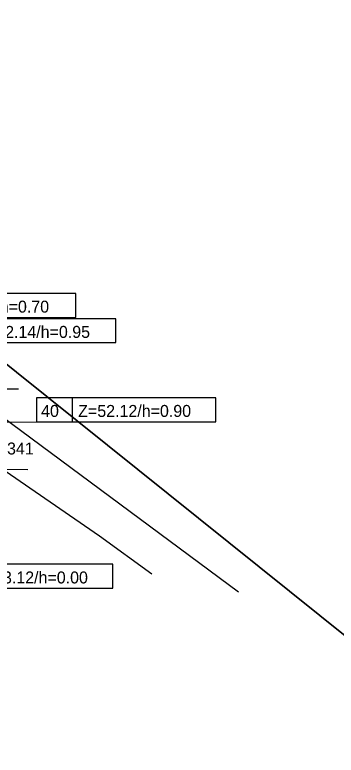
# Model space of a CAD drawing. Extents: x 592082 to 595437, y 6463338 to 6467739.
# Drawn here: x 592422.46 to 592441.27, y 6466209.39 to 6466252.72 of the extents above; entities that cross this region are included whole.
import ezdxf

# ---------------------------------------------------------------- set-up
doc = ezdxf.new("R2010")
doc.units = 0
for name, color, linetype in [('ABIJOONIS', 7, 'Continuous'), ('MPKAABEL', 7, 'Continuous'), ('PIIR', 7, 'Continuous'), ('TEE', 7, 'Continuous')]:
    doc.layers.add(name, color=color, linetype=linetype)

msp = doc.modelspace()

# ---------------------------------------------------------------- linework, layer by layer
at = {"layer": 'ABIJOONIS'}
for points in [[(592405.513, 6466234.668), (592415.526, 6466235.012), (592426.026, 6466235.012), (592426.026, 6466236.412), (592415.526, 6466236.412), (592415.526, 6466235.012)], [(592405.926, 6466232.295), (592417.871, 6466233.534), (592428.371, 6466233.534), (592428.371, 6466234.934), (592417.871, 6466234.934), (592417.871, 6466233.534)], [(592406.326, 6466228.858), (592423.735, 6466228.908), (592434.235, 6466228.908), (592434.235, 6466230.308), (592423.735, 6466230.308), (592423.735, 6466228.908)], [(592425.835, 6466228.908), (592425.835, 6466230.308)], [(592408.036, 6466224.039), (592417.694, 6466219.162), (592428.194, 6466219.162), (592428.194, 6466220.562), (592417.694, 6466220.562), (592417.694, 6466219.162)]]:
    msp.add_lwpolyline(points, dxfattribs=at)
at = {"layer": 'MPKAABEL'}
for points in [[(592405.954, 6466229.159), (592416.935, 6466230.832), (592422.676, 6466230.832)], [(592406.175, 6466228.523), (592418.139, 6466226.158), (592423.218, 6466226.12)]]:
    msp.add_lwpolyline(points, dxfattribs=at)
at = {"layer": 'PIIR'}
for points in [[(592657.41, 6466097.76), (592652.06, 6466095.54), (592644.52, 6466091.39), (592640.79, 6466094.86), (592580.24, 6466151.13), (592638.14, 6466227.31), (592632.64, 6466231.08), (592575.1, 6466268.95), (592519.66, 6466188.46), (592504.75, 6466166.17), (592481.06, 6466184.88), (592411.88, 6466240.36), (592457.87, 6466368.11), (592467.6, 6466449.28), (592507.21, 6466454.09), (592542.01, 6466457.71), (592673.55, 6466470.91)], [(592365.98, 6466124.11), (592372.7, 6466240.06), (592368.77, 6466376.93), (592364.1, 6466392.22), (592386.8, 6466438.64), (592386.7, 6466439.56), (592467.6, 6466449.28), (592457.87, 6466368.11), (592411.88, 6466240.36), (592481.06, 6466184.88)]]:
    msp.add_lwpolyline(points, dxfattribs=at)
at = {"layer": 'TEE'}
for points in [[(592408.764, 6466249.828), (592407.446, 6466245.456), (592406.752, 6466242.846), (592406.442, 6466240.502), (592406.831, 6466238.914), (592407.484, 6466237.872), (592408.832, 6466236.834), (592411.597, 6466233.841), (592415.522, 6466230.408), (592427.423, 6466222.233), (592430.48, 6466220.001)], [(592411.588, 6466248.997), (592410.668, 6466245.515), (592410.452, 6466243.109), (592410.704, 6466240.295), (592412.074, 6466237.234), (592413.527, 6466235.334), (592415.348, 6466233.608), (592420.503, 6466230.085), (592435.553, 6466218.947)]]:
    msp.add_lwpolyline(points, dxfattribs=at)

# ---------------------------------------------------------------- texts
at = {"layer": 'ABIJOONIS'}
for s, p in [('Z=52.42/h=0.70', (592417.853, 6466235.292)), ('Z=52.14/h=0.95', (592420.251, 6466233.814)), ('40', (592423.997, 6466229.188)), ('Z=52.12/h=0.90', (592426.167, 6466229.188)), ('Z=53.12/h=0.00', (592420.126, 6466219.442))]:
    msp.add_text(s, height=0.7, dxfattribs=at).set_placement(p)
at = {"layer": 'MPKAABEL'}
msp.add_text('MPL 180341', height=0.7, dxfattribs=at).set_placement((592418.256, 6466226.99))

doc.saveas('drawing.dxf')
